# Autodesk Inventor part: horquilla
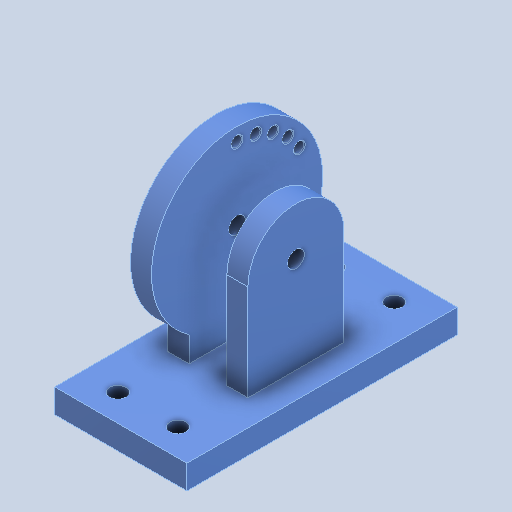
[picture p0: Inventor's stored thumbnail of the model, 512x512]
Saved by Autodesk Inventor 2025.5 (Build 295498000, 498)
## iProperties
Created: 2026-10
Part Number: horquilla
Material: Genérico
Document SubType Name: Modeling
Designer: Luis M
Density: 1 g/cm^3
Appearance: Valor por defecto
Author: Luis M
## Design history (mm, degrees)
feature "Base1"
node "Sólido1"
